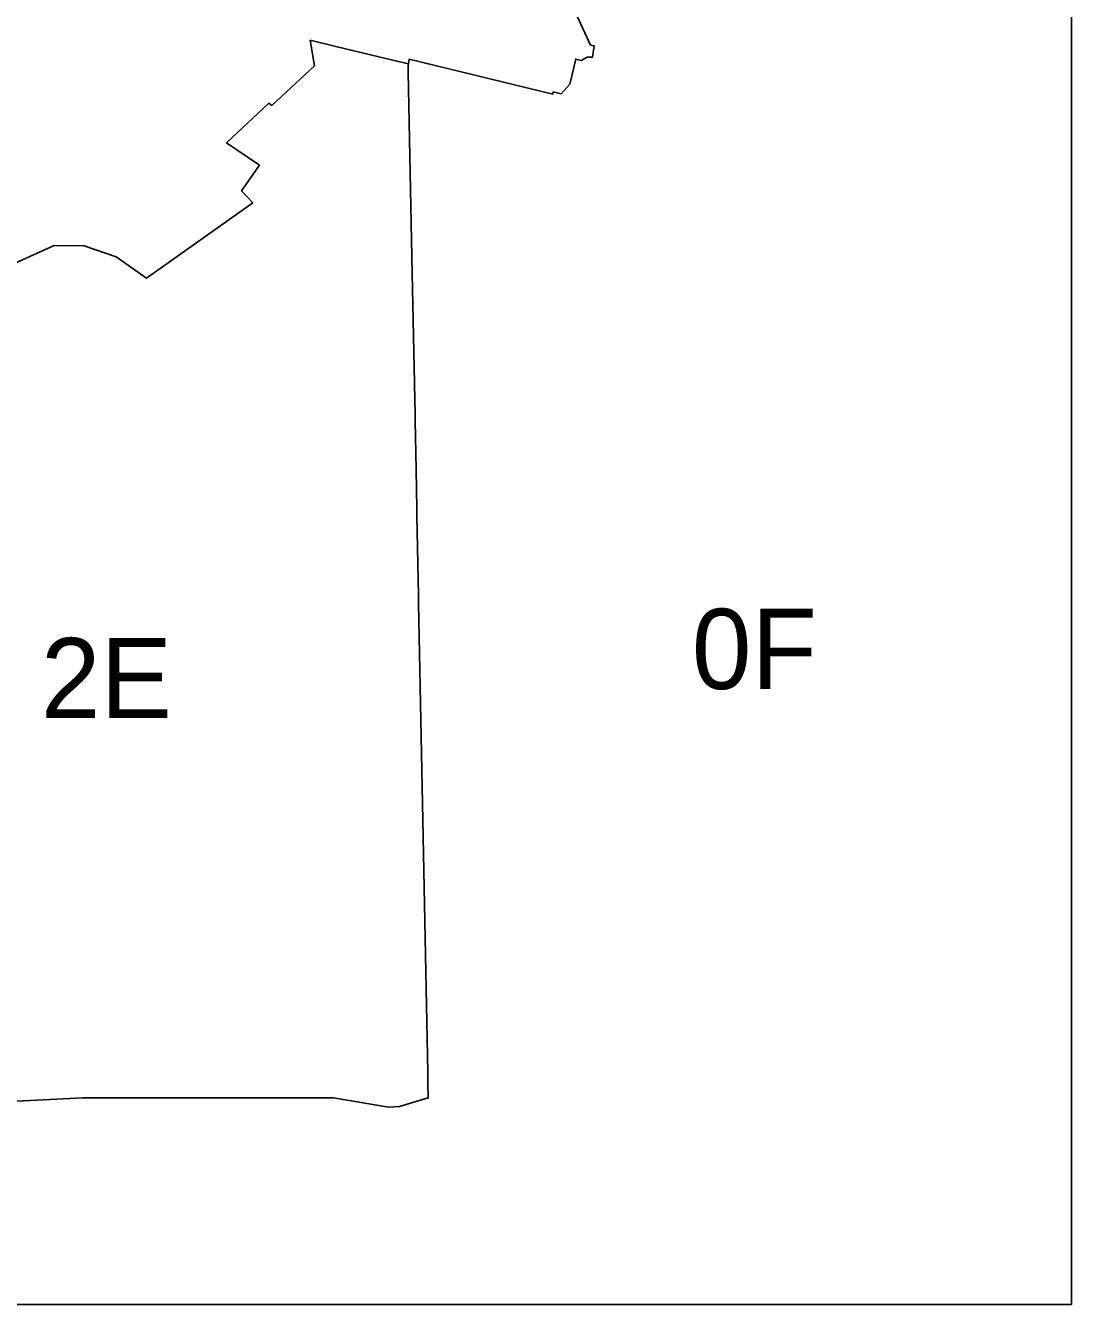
# Model space of a CAD drawing. Extents: x 152750 to 166250, y 378996 to 390000.
# Drawn here: x 163640 to 166250, y 379000 to 382190 of the extents above; entities that cross this region are included whole.
import ezdxf

# ---------------------------------------------------------------- set-up
doc = ezdxf.new("R2010")
doc.units = 0
doc.layers.add('BLT_Nummers', color=7, linetype='Continuous')
doc.layers.add('BLT_Shapes', color=7, linetype='Continuous')

msp = doc.modelspace()

# ---------------------------------------------------------------- linework, layer by layer
at = {"layer": 'BLT_Shapes'}
for p, q in [((164597.3, 382106.4), (164597.3, 382106.4)), ((164207.4, 381747.9), (163942.4, 381560.3)), ((163942.4, 381560.3), (163866.1, 381613.5)), ((164606.1, 381533.3), (164605.3, 381572.1)), ((164612.3, 381219.4), (164606.1, 381533.3)), ((164612.6, 381202.8), (164612.3, 381219.4)), ((164613.4, 381165.3), (164612.6, 381202.8)), ((164643.8, 379579), (164630.8, 380250)), ((163500, 379501.2), (163783.7, 379515.1)), ((163783.7, 379515.1), (163903.5, 379515.1))]:
    msp.add_line(p, q, dxfattribs=at)
for points in [[(163165.3, 379000), (166250, 379000), (166250, 382867.2)], [(165017, 382214.3), (165050.1, 382141.6), (165059, 382140.3), (165054.8, 382111.4), (165041.8, 382111.9), (165026.9, 382103.6), (165013.2, 382106.8), (164998.3, 382044.3), (164976.5, 382020.4), (164957, 382025.1), (164955.6, 382019.4), (164597.4, 382106.6), (164595.7, 382095.2), (164595.1, 382090.8), (164595.4, 382074.4), (164605.3, 381572.1), (164606.1, 381533.3), (164612.3, 381219.4), (164612.6, 381202.8), (164613.4, 381165.3), (164614.8, 381082), (164616.7, 380986.6), (164617, 380967.9), (164620.8, 380769.2), (164621.2, 380749.4), (164630.8, 380250), (164643.8, 379579), (164643.9, 379571.5), (164644, 379564.6), (164644.5, 379542.7), (164644.9, 379521.1), (164645, 379515.2), (164573.8, 379493.6), (164545.8, 379492.2), (164408.4, 379515), (163942.9, 379515.1), (163931.8, 379515.1), (163916.8, 379515.1), (163903.5, 379515.1), (163783.7, 379515.1), (163500, 379501.2)], [(165054.8, 382111.4), (165059, 382140.2), (165050, 382141.5), (165017, 382214.1), (165017, 382214.3)], [(163264.5, 381641.7), (163282.2, 381626), (163296.9, 381615.3), (163314.5, 381604.6), (163428.9, 381541), (163443.8, 381532.9), (163451.5, 381529.6), (163459.2, 381527.8), (163468.4, 381527.4), (163483.1, 381532.5), (163607.3, 381594.2), (163711.5, 381641.4), (163786.2, 381641.2), (163866.1, 381613.5), (163942.4, 381560.3), (164207.4, 381747.9), (164179.4, 381777.8), (164224.1, 381842.1), (164141.8, 381898.3), (164247.7, 381997), (164254.9, 381991.3), (164361.7, 382090.3), (164350.9, 382154.3)], [(164350.9, 382154.3), (164361.7, 382090.3), (164254.9, 381991.3), (164247.7, 381997), (164141.8, 381898.3)], [(164350.9, 382154.3), (164414.5, 382138.6), (164542.9, 382107.4), (164595.7, 382095.1)], [(164595.7, 382095.1), (164542.9, 382107.4), (164414.5, 382138.6), (164350.9, 382154.3)], [(164605.3, 381572.1), (164595.4, 382074.4), (164595.1, 382090.8), (164595.7, 382095.1)], [(164595.7, 382095.1), (164595.7, 382095.2), (164597.3, 382106.4)], [(164597.3, 382106.4), (164597.4, 382106.6), (164955.6, 382019.4), (164957, 382025.1), (164976.5, 382020.4), (164998.3, 382044.3), (165013.2, 382106.8), (165026.9, 382103.6), (165041.8, 382111.9), (165054.8, 382111.4)], [(164141.8, 381898.3), (164224.1, 381842.1), (164179.4, 381777.8), (164207.4, 381747.9)], [(163711.5, 381641.4), (163607.3, 381594.2), (163483.1, 381532.5)], [(163866.1, 381613.5), (163786.2, 381641.2), (163711.5, 381641.4)], [(164630.8, 380250), (164621.2, 380749.4), (164620.8, 380769.2), (164617, 380967.9), (164616.7, 380986.6), (164614.8, 381082), (164613.4, 381165.3)], [(164408.4, 379515), (164545.8, 379492.2), (164573.8, 379493.6), (164645, 379515.2), (164644.9, 379521.1), (164644.5, 379542.7), (164644, 379564.6), (164643.9, 379571.5), (164643.8, 379579)], [(163903.5, 379515.1), (163916.8, 379515.1), (163931.8, 379515.1), (163942.9, 379515.1), (164408.4, 379515)]]:
    msp.add_lwpolyline(points, dxfattribs=at)

# ---------------------------------------------------------------- texts
at = {"layer": 'BLT_Nummers'}
for s, p in [('0F', (165302.9, 380535.4)), ('2E', (163678.6, 380462.6))]:
    msp.add_text(s, height=200, dxfattribs=at).set_placement(p)

doc.saveas('drawing.dxf')
